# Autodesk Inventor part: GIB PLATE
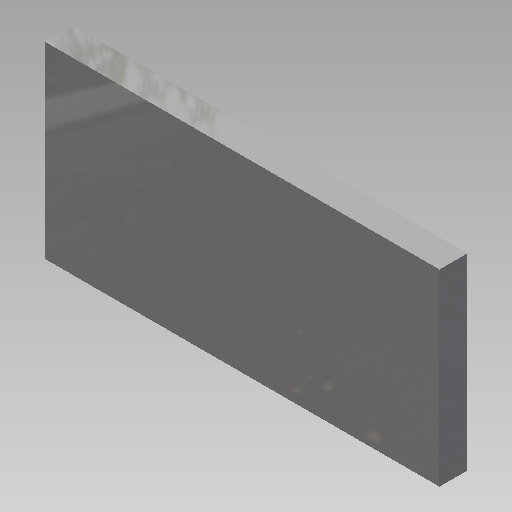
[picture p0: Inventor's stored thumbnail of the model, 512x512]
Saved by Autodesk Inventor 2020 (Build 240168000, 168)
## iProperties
Part Number: GIB PLATE
Document SubType Name: Modeling
Created: 2003-11
Designer: Autodesk, Inc.
Manufacturer: Standard
Standards Organization: Custom
Mass: 9.81371 g
Surface Area: 12.9097 cm^2
Volume: 1.25015 cm^3
Density: 7.85 g/cm^3
Material: Steel, Mild
Appearance: Steel
Control State: 0
Master: False
Checked Out: False
Shininess: 64.0
Length Units: 11272
Angle Units: 11279
Time Units: 11290
Mass Units: 11286
Length Display Precision: 3
Angle Display Precision: 2
Compacted: True
Density: 0.0
Volumn: 0.0
Area: 0.0
PropertySet Name: Model Information
Author: Autodesk, Inc.
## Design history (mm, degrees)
sketch "Sketch1"
  geometry: L1 (0, 0)-(33.338, 0); L2 (33.338, 0)-(33.338, 15.875); L3 (33.338, 15.875)-(0, 15.875); L4 (0, 15.875)-(0, 0)
  constraints: 8 end point, 2 parallel, 1 horizontal, 1 perpendicular
  dimensions: "d0" = 33.3375 distance of L1.start L1.end; "d1" = 15.875 distance between parallel lines of L1 L3
extrude "Extrusion1" new body sketch "Sketch1" distance "d2" = 2.3622; taper "d3" = 0 deg
body "Solid1"
